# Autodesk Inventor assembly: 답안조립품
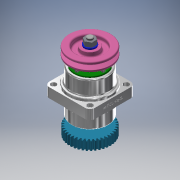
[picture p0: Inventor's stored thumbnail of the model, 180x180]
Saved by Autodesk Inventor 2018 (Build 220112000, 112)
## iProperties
Created: 2023-10
Part Number: 답안조립품
Material: 일반
Document SubType Name: Assembly
Designer: home
Author: home
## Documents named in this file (12)
- C:\Users\home\Desktop\731006V1009\답안조립품.iam
- C:\Users\home\Desktop\731006V1009\본체.ipt
- C:\Users\home\Desktop\731006V1009\베어링 6204.ipt
- C:\Users\home\Desktop\731006V1009\커버.ipt
- C:\Users\home\Desktop\731006V1009\볼트 M4x0.7.ipt
- C:\Users\home\Desktop\731006V1009\오일실 20x35x8.ipt
- C:\Users\home\Desktop\731006V1009\축.ipt
- C:\Users\home\Desktop\731006V1009\키 5x5.ipt
- C:\Users\home\Desktop\731006V1009\스퍼기어.ipt
- C:\Users\home\Desktop\731006V1009\와셔 12x24.ipt
- C:\Users\home\Desktop\731006V1009\너트 M12x1.25.ipt
- C:\Users\home\Desktop\731006V1009\V벨트풀리.ipt
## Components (1 placed, 1 different names)
1. V벨트풀리:1
